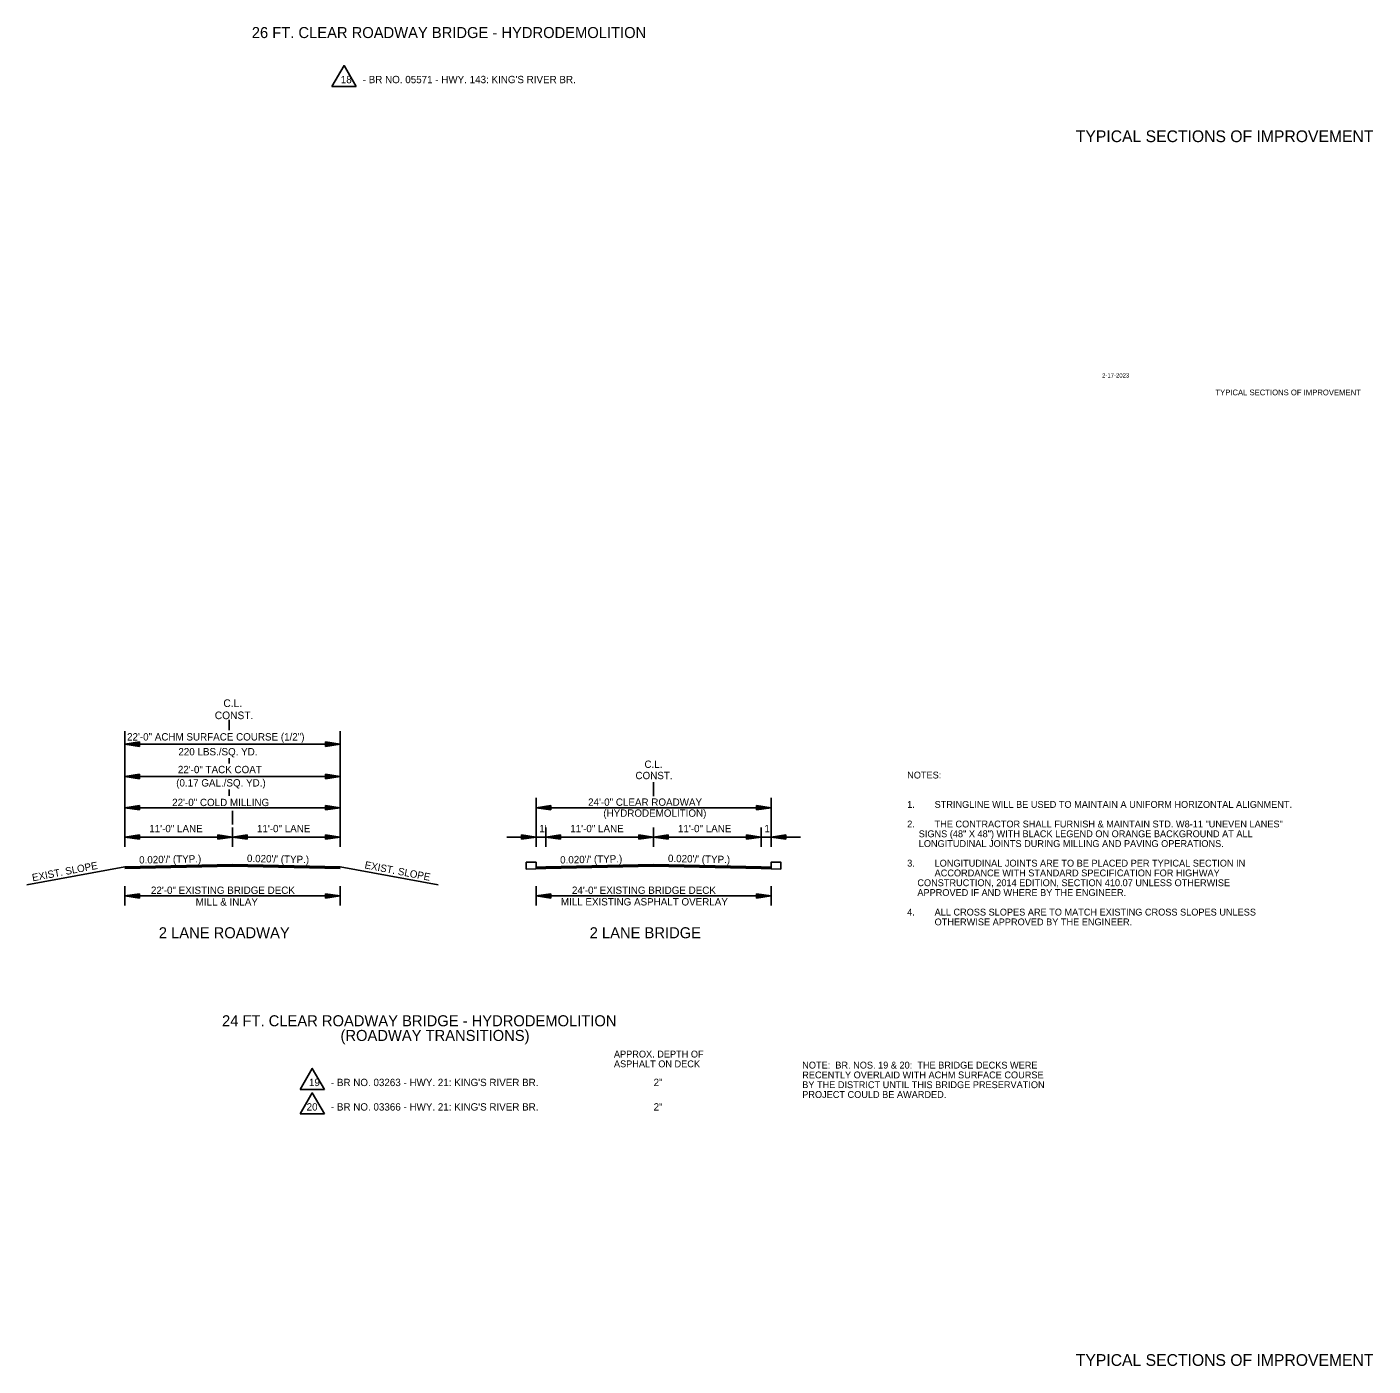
# Model space of a CAD drawing. Extents: x 549600 to 1930787, y -1955432 to 596640.
# Drawn here: x 551171 to 552546, y -1955432 to -1954064 of the extents above; entities that cross this region are included whole.
import ezdxf

# ---------------------------------------------------------------- set-up
doc = ezdxf.new("R2010")
doc.units = 0
for name, color, linetype in [('R_Border', 7, 'Continuous'), ('R_Border Notes', 7, 'Continuous'), ('R_Border Prem', 7, 'Continuous'), ('S_AREA_CALC', 7, 'Continuous')]:
    doc.layers.add(name, color=color, linetype=linetype)

# ---------------------------------------------------------------- blocks, each defined once
blk = doc.blocks.new('ARROW')
at = {"layer": 'S_AREA_CALC'}
for p, q in [((-2, 0.3), (0, 0)), ((-2, 0.3), (-2, -0.3)), ((-2, 0.25), (-0.334, 0)), ((-2, 0.199), (-0.678, 0)), ((-2, 0.149), (-1.011, 0)), ((-2, 0.097), (-1.35, 0)), ((-2, 0.047), (-1.684, 0)), ((-2, -0.3), (0, 0)), ((-2, -0.098), (-1.35, 0)), ((-2, -0.199), (-0.678, 0)), ((-2, -0.25), (-0.334, 0)), ((-2, -0.149), (-1.011, 0)), ((-2, -0.047), (-1.684, 0))]:
    blk.add_line(p, q, dxfattribs=at)

msp = doc.modelspace()

# ---------------------------------------------------------------- linework, layer by layer
at = {"layer": 'R_Border'}
for p, q in [((551482.6, -1954125.3), (551507.4, -1954125.3)), ((551811.1, -1954835.8), (551811.1, -1954850.3)), ((551271.1, -1954852), (551271.1, -1954902)), ((551491.1, -1954852), (551491.1, -1954902)), ((551691.1, -1954852), (551691.1, -1954902)), ((551931.1, -1954852), (551931.1, -1954902)), ((551271.1, -1954862), (551491.1, -1954862)), ((551381.1, -1954865), (551381.1, -1954879)), ((551691.1, -1954862), (551931.1, -1954862)), ((551381.1, -1954882), (551381.1, -1954902)), ((551701.1, -1954882), (551701.1, -1954902)), ((551811.1, -1954882), (551811.1, -1954902)), ((551921.1, -1954882), (551921.1, -1954902)), ((551271.1, -1954892), (551491.1, -1954892)), ((551661.1, -1954892), (551961.1, -1954892)), ((551271.1, -1954942), (551271.1, -1954962)), ((551491.1, -1954942), (551491.1, -1954962)), ((551691.1, -1954942), (551691.1, -1954962)), ((551931.1, -1954942), (551931.1, -1954962)), ((551271.1, -1954952), (551491.1, -1954952)), ((551691.1, -1954952), (551931.1, -1954952)), ((551450.1, -1955149.7), (551474.9, -1955149.7)), ((551450.1, -1955174.7), (551474.9, -1955174.7))]:
    msp.add_line(p, q, dxfattribs=at)
for points in [[(551507.4, -1954125.3), (551495, -1954103.9), (551482.6, -1954125.3)], [(551271.1, -1954922.2), (551381.1, -1954920), (551491.1, -1954922.2)], [(551271.1, -1954922.5), (551381.1, -1954920.3), (551491.1, -1954922.5)], [(551271.1, -1954922.8), (551381.1, -1954920.6), (551491.1, -1954922.8)], [(551271.1, -1954923.1), (551381.1, -1954920.9), (551491.1, -1954923.1)], [(551271.1, -1954923.4), (551381.1, -1954921.2), (551491.1, -1954923.4)], [(551271.1, -1954923.7), (551381.1, -1954921.5), (551491.1, -1954923.7)], [(551271.1, -1954924), (551381.1, -1954921.8), (551491.1, -1954924)], [(551691.1, -1954924.1), (551691.1, -1954917.6), (551681.1, -1954917.6), (551681.1, -1954924.8)], [(551681.1, -1954924.8), (551701.1, -1954924), (551811.1, -1954921.8), (551921.1, -1954924), (551941.1, -1954924.8)], [(551691.1, -1954922.6), (551701.1, -1954922.2), (551811.1, -1954920), (551921.1, -1954922.2), (551931.1, -1954922.6)], [(551691.1, -1954922.9), (551701.1, -1954922.5), (551811.1, -1954920.3), (551921.1, -1954922.5), (551931.1, -1954922.9)], [(551691.1, -1954923.2), (551701.1, -1954922.8), (551811.1, -1954920.6), (551921.1, -1954922.8), (551931.1, -1954923.2)], [(551691.1, -1954923.5), (551701.1, -1954923.1), (551811.1, -1954920.9), (551921.1, -1954923.1), (551931.1, -1954923.5)], [(551691.1, -1954923.8), (551701.1, -1954923.4), (551811.1, -1954921.2), (551921.1, -1954923.4), (551931.1, -1954923.8)], [(551691.1, -1954924.1), (551701.1, -1954923.7), (551811.1, -1954921.5), (551921.1, -1954923.7), (551931.1, -1954924.1)], [(551931.1, -1954924.8), (551931.1, -1954917.6), (551941.1, -1954917.6), (551941.1, -1954924.8)], [(551474.9, -1955149.7), (551462.5, -1955128.2), (551450.1, -1955149.7)], [(551474.9, -1955174.7), (551462.5, -1955153.2), (551450.1, -1955174.7)]]:
    msp.add_lwpolyline(points, dxfattribs=at)
at = {"layer": 'S_AREA_CALC'}
for p, q in [((551377.6, -1954782.6), (551377.6, -1954772.2)), ((551271.1, -1954900), (551271.1, -1954783.7)), ((551491.1, -1954900.5), (551491.1, -1954783.7)), ((551286.1, -1954794.8), (551271.1, -1954797)), ((551271.1, -1954797), (551491.1, -1954797)), ((551286.1, -1954799.3), (551271.1, -1954797)), ((551286.1, -1954795.2), (551273.6, -1954797)), ((551286.1, -1954798.9), (551273.6, -1954797)), ((551286.1, -1954795.5), (551276.2, -1954797)), ((551286.1, -1954798.5), (551276.2, -1954797)), ((551286.1, -1954795.9), (551278.7, -1954797)), ((551286.1, -1954798.2), (551278.7, -1954797)), ((551286.1, -1954796.3), (551281.2, -1954797)), ((551286.1, -1954797.8), (551281.2, -1954797)), ((551286.1, -1954796.7), (551283.7, -1954797)), ((551286.1, -1954797.4), (551283.7, -1954797)), ((551286.1, -1954799.3), (551286.1, -1954794.8)), ((551476.1, -1954794.8), (551491.1, -1954797)), ((551476.1, -1954794.8), (551476.1, -1954799.3)), ((551476.1, -1954795.2), (551488.6, -1954797)), ((551476.1, -1954795.5), (551486, -1954797)), ((551476.1, -1954795.9), (551483.5, -1954797)), ((551476.1, -1954796.3), (551481, -1954797)), ((551476.1, -1954796.7), (551478.5, -1954797)), ((551476.1, -1954799.3), (551491.1, -1954797)), ((551476.1, -1954797.8), (551481, -1954797)), ((551476.1, -1954798.5), (551486, -1954797)), ((551476.1, -1954798.9), (551488.6, -1954797)), ((551476.1, -1954798.2), (551483.5, -1954797)), ((551476.1, -1954797.4), (551478.5, -1954797)), ((551377.6, -1954816.8), (551377.6, -1954811.2)), ((551286.1, -1954827.8), (551271.1, -1954830)), ((551271.1, -1954830), (551491.1, -1954830)), ((551286.1, -1954832.3), (551271.1, -1954830)), ((551286.1, -1954828.1), (551273.6, -1954830)), ((551286.1, -1954831.9), (551273.6, -1954830)), ((551286.1, -1954828.5), (551276.2, -1954830)), ((551286.1, -1954831.5), (551276.2, -1954830)), ((551286.1, -1954828.9), (551278.7, -1954830)), ((551286.1, -1954831.1), (551278.7, -1954830)), ((551286.1, -1954829.3), (551281.2, -1954830)), ((551286.1, -1954830.7), (551281.2, -1954830)), ((551286.1, -1954829.7), (551283.7, -1954830)), ((551286.1, -1954830.4), (551283.7, -1954830)), ((551286.1, -1954832.3), (551286.1, -1954827.8)), ((551476.1, -1954827.8), (551491.1, -1954830)), ((551476.1, -1954827.8), (551476.1, -1954832.3)), ((551476.1, -1954828.1), (551488.6, -1954830)), ((551476.1, -1954828.5), (551486, -1954830)), ((551476.1, -1954828.9), (551483.5, -1954830)), ((551476.1, -1954829.3), (551481, -1954830)), ((551476.1, -1954829.7), (551478.5, -1954830)), ((551476.1, -1954832.3), (551491.1, -1954830)), ((551476.1, -1954830.7), (551481, -1954830)), ((551476.1, -1954831.5), (551486, -1954830)), ((551476.1, -1954831.9), (551488.6, -1954830)), ((551476.1, -1954831.1), (551483.5, -1954830)), ((551476.1, -1954830.4), (551478.5, -1954830)), ((551377.6, -1954849.7), (551377.6, -1954843.3)), ((551286.1, -1954859.7), (551271.1, -1954862)), ((551286.1, -1954860.1), (551273.6, -1954862)), ((551286.1, -1954860.5), (551276.2, -1954862)), ((551286.1, -1954860.9), (551278.7, -1954862)), ((551286.1, -1954861.2), (551281.2, -1954862)), ((551286.1, -1954861.6), (551283.7, -1954862)), ((551286.1, -1954864.2), (551286.1, -1954859.7)), ((551476.1, -1954859.7), (551491.1, -1954862)), ((551476.1, -1954859.7), (551476.1, -1954864.2)), ((551476.1, -1954860.1), (551488.6, -1954862)), ((551476.1, -1954860.5), (551486, -1954862)), ((551476.1, -1954860.9), (551483.5, -1954862)), ((551476.1, -1954861.3), (551481, -1954862)), ((551476.1, -1954861.6), (551478.5, -1954862)), ((551271.1, -1954862), (551491.1, -1954862)), ((551286.1, -1954864.2), (551271.1, -1954862)), ((551286.1, -1954863.9), (551273.6, -1954862)), ((551286.1, -1954863.5), (551276.2, -1954862)), ((551286.1, -1954863.1), (551278.7, -1954862)), ((551286.1, -1954862.7), (551281.2, -1954862)), ((551286.1, -1954862.3), (551283.7, -1954862)), ((551476.1, -1954864.2), (551491.1, -1954862)), ((551476.1, -1954862.7), (551481, -1954862)), ((551476.1, -1954863.5), (551486, -1954862)), ((551476.1, -1954863.9), (551488.6, -1954862)), ((551476.1, -1954863.1), (551483.5, -1954862)), ((551476.1, -1954862.3), (551478.5, -1954862)), ((551271.1, -1954922.2), (551171, -1954940.6)), ((551491.1, -1954922.2), (551591.2, -1954940.6))]:
    msp.add_line(p, q, dxfattribs=at)

# ---------------------------------------------------------------- block references
at = {"layer": 'R_Border', "xscale": 7.5, "yscale": 7.5, "rotation": 180}
for p in [(551271.1, -1954862), (551691.1, -1954862), (551271.1, -1954892), (551381.1, -1954892), (551701.1, -1954892), (551811.1, -1954892), (551931.1, -1954892), (551271.1, -1954952), (551691.1, -1954952)]:
    msp.add_blockref('ARROW', p, dxfattribs=at)
at = {"layer": 'R_Border', "xscale": 7.5, "yscale": 7.5}
for p in [(551491.1, -1954862), (551931.1, -1954862), (551381.1, -1954892), (551491.1, -1954892), (551691.1, -1954892), (551811.1, -1954892), (551921.1, -1954892), (551491.1, -1954952), (551931.1, -1954952)]:
    msp.add_blockref('ARROW', p, dxfattribs=at)

# ---------------------------------------------------------------- texts
at = {"layer": 'R_Border'}
for s, height, p in [('18', 7.5, (551491.6, -1954121.9)), ("- BR NO. 05571 - HWY. 143: KING'S RIVER BR.", 7.5, (551514, -1954121.9)), ('C.L.', 7.5, (551801.8, -1954821.3)), ('CONST.', 7.5, (551792.6, -1954832.8)), ('24\'-0" CLEAR ROADWAY', 7.5, (551744.2, -1954860)), ('(HYDRODEMOLITION)', 7.5, (551759.7, -1954871.2)), ('11\'-0" LANE', 7.5, (551296, -1954887)), ('11\'-0" LANE', 7.5, (551406, -1954887)), ("1'", 7.5, (551694.3, -1954887)), ('11\'-0" LANE', 7.5, (551726, -1954887)), ('11\'-0" LANE', 7.5, (551836, -1954887)), ("1'", 7.5, (551924.3, -1954887)), ('22\'-0" EXISTING BRIDGE DECK', 7.5, (551297.7, -1954950)), ('24\'-0" EXISTING BRIDGE DECK', 7.5, (551727.7, -1954950)), ('2 LANE ROADWAY', 11.25, (551305.7, -1954995.3)), ('2 LANE BRIDGE', 11.25, (551745.8, -1954995.3)), ('24 FT. CLEAR ROADWAY BRIDGE - HYDRODEMOLITION', 11.25, (551370.3, -1955085.2)), ('(ROADWAY TRANSITIONS)', 11.25, (551491.3, -1955100.2)), ('19', 7.5, (551459.1, -1955146.3)), ("- BR NO. 03263 - HWY. 21: KING'S RIVER BR.", 7.5, (551481.5, -1955146.3)), ('2"', 7.5, (551811.1, -1955146.3)), ('20', 7.5, (551456.7, -1955171.3)), ("- BR NO. 03366 - HWY. 21: KING'S RIVER BR.", 7.5, (551481.5, -1955171.3)), ('2"', 7.5, (551811.1, -1955171.3))]:
    msp.add_text(s, height=height, dxfattribs=at).set_placement(p)
for s, height, rotation, p in [('TYPICAL SECTIONS OF IMPROVEMENT', 12, 360, (552242.3, -1954182.1)), ("0.020'/' (TYP.)", 7.5, 1.1458, (551285.7, -1954919)), ("0.020'/' (TYP.)", 7.5, 358.8542, (551395.7, -1954917.4)), ("0.020'/' (TYP.)", 7.5, 1.1458, (551715.7, -1954919)), ("0.020'/' (TYP.)", 7.5, 358.8542, (551825.7, -1954917.4)), ('TYPICAL SECTIONS OF IMPROVEMENT', 12, 360, (552242.3, -1955432.1))]:
    msp.add_text(s, height=height, rotation=rotation, dxfattribs=at).set_placement(p)
at = {"layer": 'R_Border Notes'}
for s, p in [('NOTES: ', (552070.1, -1954832.1)), ('1.', (552070.1, -1954862.1)), ('STRINGLINE WILL BE USED TO MAINTAIN A UNIFORM HORIZONTAL ALIGNMENT.', (552098.1, -1954862.1)), ('2.', (552070.1, -1954882.1)), ('THE CONTRACTOR SHALL FURNISH & MAINTAIN STD. W8-11 "UNEVEN LANES" ', (552098.1, -1954882.1)), ('    SIGNS (48" X 48") WITH BLACK LEGEND ON ORANGE BACKGROUND AT ALL ', (552071.5, -1954892.1)), ('    LONGITUDINAL JOINTS DURING MILLING AND PAVING OPERATIONS.', (552071.5, -1954902.1)), ('3.', (552070.1, -1954922.1)), ('LONGITUDINAL JOINTS ARE TO BE PLACED PER TYPICAL SECTION IN ', (552098.1, -1954922.1)), ('ACCORDANCE WITH STANDARD SPECIFICATION FOR HIGHWAY', (552098.1, -1954932.1)), ('    CONSTRUCTION, 2014 EDITION, SECTION 410.07 UNLESS OTHERWISE', (552070.1, -1954942.1)), ('    APPROVED IF AND WHERE BY THE ENGINEER.', (552070.1, -1954952.1)), ('4.', (552070.1, -1954972.1)), ('ALL CROSS SLOPES ARE TO MATCH EXISTING CROSS SLOPES UNLESS ', (552098.1, -1954972.1)), ('OTHERWISE APPROVED BY THE ENGINEER.', (552098.1, -1954982.1)), ('APPROX. DEPTH OF', (551770.6, -1955117.1)), ('ASPHALT ON DECK', (551770.6, -1955127.1)), ('NOTE:  BR. NOS. 19 & 20:  THE BRIDGE DECKS WERE ', (551962.9, -1955128.4)), ('RECENTLY OVERLAID WITH ACHM SURFACE COURSE', (551962.9, -1955138.4)), ('BY THE DISTRICT UNTIL THIS BRIDGE PRESERVATION', (551962.9, -1955148.4)), ('PROJECT COULD BE AWARDED.', (551962.9, -1955158.4))]:
    msp.add_text(s, height=7, dxfattribs=at).set_placement(p)
at = {"layer": 'R_Border Prem'}
msp.add_text('2-17-2023', height=4.4, dxfattribs=at).set_placement((552269.2, -1954422.6))
msp.add_text('TYPICAL SECTIONS OF IMPROVEMENT', height=5.862, rotation=360, dxfattribs=at).set_placement((552384.9, -1954440.7))
at = {"layer": 'S_AREA_CALC'}
for s, height, p in [('26 FT. CLEAR ROADWAY BRIDGE - HYDRODEMOLITION', 11.25, (551400.7, -1954075.8)), ('C.L.', 7.8, (551371.7, -1954759.1)), ('CONST.', 7.8, (551362.9, -1954771.5)), ('22\'-0" ACHM SURFACE COURSE (1/2")', 7.5, (551273.3, -1954793.3)), ('220 LBS./SQ. YD. ', 7.5, (551325.7, -1954808.5)), ('22\'-0" TACK COAT', 7.5, (551325.2, -1954826.7)), ('(0.17 GAL./SQ. YD.)', 7.5, (551323.5, -1954840.3)), ('22\'-0" COLD MILLING ', 7.5, (551319.4, -1954860.3)), ('MILL & INLAY', 7.5, (551343.4, -1954961.9)), ('MILL EXISTING ASPHALT OVERLAY', 7.5, (551716.4, -1954961.8))]:
    msp.add_text(s, height=height, dxfattribs=at).set_placement(p)
for rotation, p in [(349.1171, (551515.5, -1954923.8)), (10.8829, (551177, -1954937.2))]:
    msp.add_text('EXIST. SLOPE', height=7.5, rotation=rotation, dxfattribs=at).set_placement(p)

doc.saveas('drawing.dxf')
